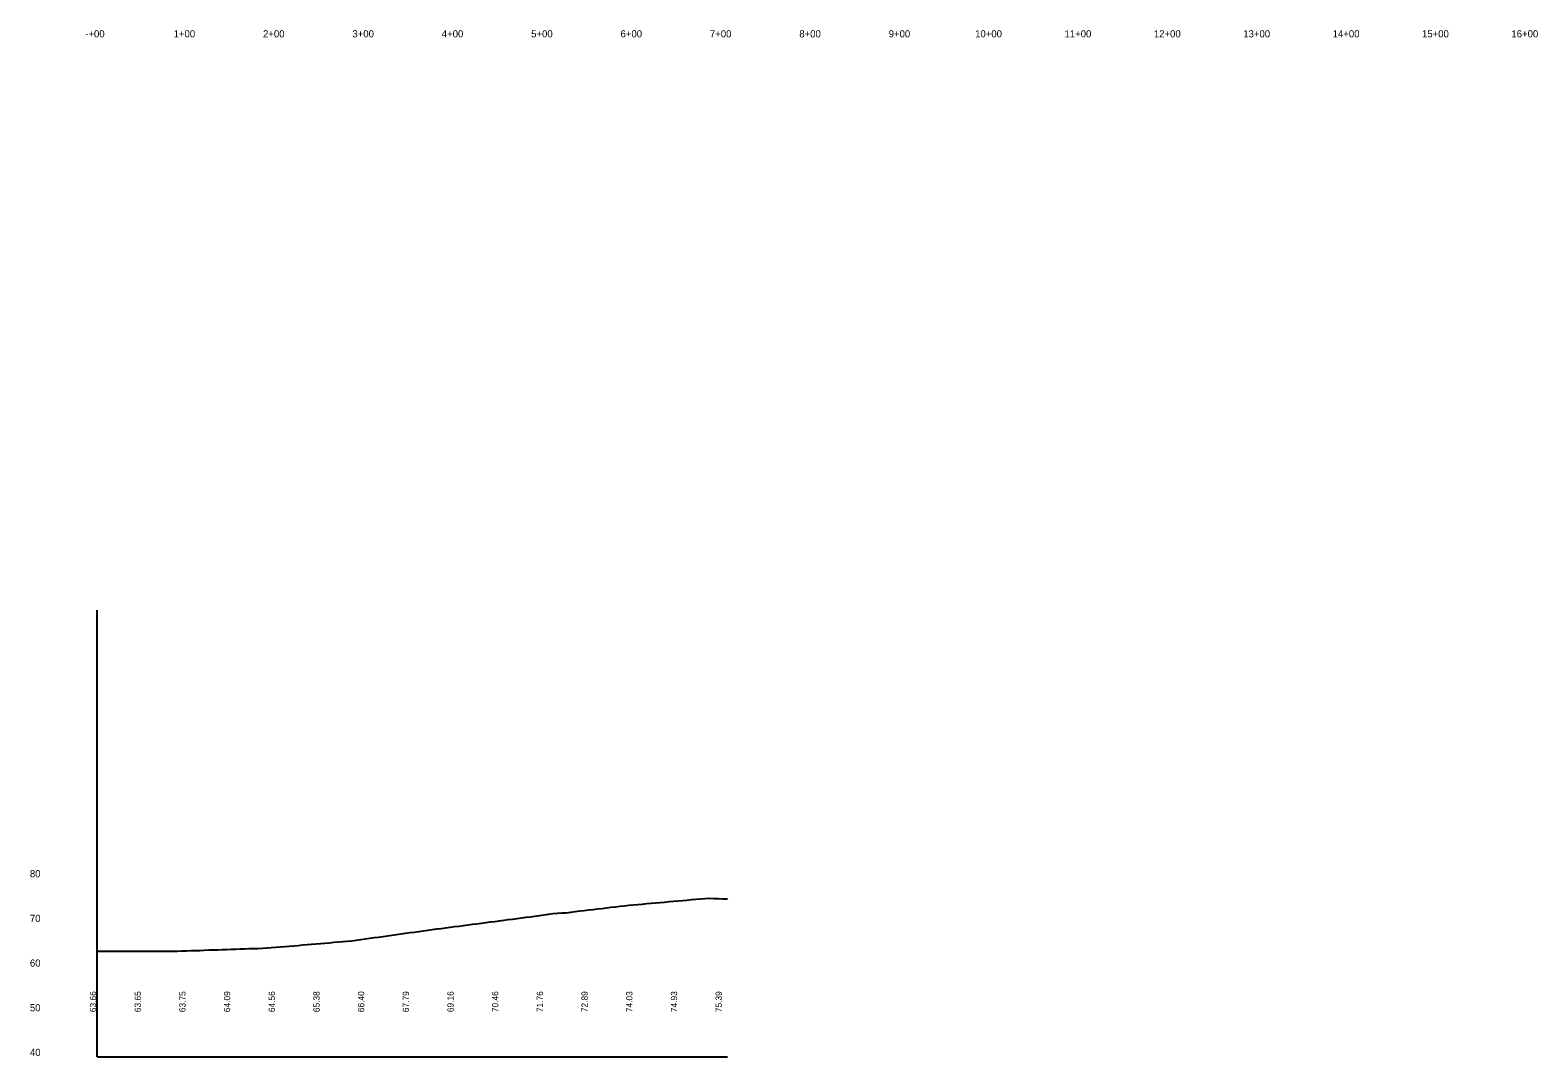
# Model space of a CAD drawing. Extents: x 2526761 to 2530854, y 882903 to 888012.
# Drawn here: x 2526764 to 2528451, y 885212 to 886361 of the extents above; entities that cross this region are included whole.
import ezdxf

# ---------------------------------------------------------------- set-up
doc = ezdxf.new("R2010")
doc.units = 0
for name, color, linetype in [('RD_DDB_ElevTX', 7, 'Continuous'), ('RD_DDB_Profile_EX', 7, 'Continuous'), ('RD_DDB_StaTX', 7, 'Continuous'), ('RD_DDB_StripGrade', 7, 'Continuous'), ('RD_GPK_Profile_Cell', 7, 'Continuous')]:
    doc.layers.add(name, color=color, linetype=linetype)

msp = doc.modelspace()

# ---------------------------------------------------------------- linework, layer by layer
at = {"layer": 'RD_DDB_Profile_EX'}
for points in [[(2527324, 885368.9), (2527329, 885369.6), (2527334, 885370.2), (2527339, 885370.9), (2527344, 885371.9), (2527349, 885372.5), (2527354, 885373), (2527359, 885373.2), (2527364, 885373.4), (2527369, 885374.2), (2527374, 885374.8), (2527379, 885375.4), (2527384, 885376), (2527389, 885376.6), (2527394, 885377.1), (2527399, 885377.7), (2527404, 885378.3), (2527409, 885378.9), (2527414, 885379.5), (2527419, 885380.1), (2527424, 885380.7), (2527429, 885381.3), (2527434, 885381.8), (2527439, 885382.2), (2527444, 885382.7), (2527449, 885383.1), (2527454, 885383.6), (2527459, 885384), (2527464, 885384.5), (2527469, 885384.9), (2527474, 885385.4), (2527479, 885385.8), (2527484, 885386.3), (2527489, 885386.7), (2527494, 885387.2), (2527499, 885387.6), (2527504, 885388.1), (2527509, 885388.5), (2527514, 885389), (2527519, 885389.5), (2527524, 885389.7), (2527529, 885389.5), (2527534, 885389.3), (2527539, 885389), (2527544, 885388.8), (2527544.4, 885388.7)], [(2526839, 885330.4), (2526864, 885330.3), (2526869, 885330.3), (2526874, 885330.3), (2526879, 885330.3), (2526884, 885330.3), (2526889, 885330.3), (2526894, 885330.3), (2526899, 885330.3), (2526904, 885330.3), (2526909, 885330.4), (2526914, 885330.4), (2526919, 885330.4), (2526924, 885330.4), (2526929, 885330.5), (2526934, 885330.6), (2526939, 885330.8), (2526944, 885331), (2526949, 885331.2), (2526954, 885331.3), (2526959, 885331.5), (2526964, 885331.7), (2526969, 885331.9), (2526974, 885332), (2526979, 885332.2), (2526984, 885332.4), (2526989, 885332.5), (2526994, 885332.7), (2526999, 885332.9), (2527004, 885333), (2527009, 885333.2), (2527014, 885333.4), (2527019, 885333.5), (2527024, 885333.7), (2527029, 885334), (2527034, 885334.5), (2527039, 885334.9), (2527044, 885335.3), (2527049, 885335.7), (2527054, 885336.1), (2527059, 885336.5), (2527064, 885336.9), (2527069, 885337.4), (2527074, 885337.8), (2527079, 885338.2), (2527084, 885338.6), (2527089, 885339), (2527094, 885339.4), (2527099, 885339.8), (2527104, 885340.3), (2527109, 885340.7), (2527114, 885341.1), (2527119, 885341.5), (2527124, 885342), (2527129, 885342.7), (2527134, 885343.4), (2527139, 885344.1), (2527144, 885344.8), (2527149, 885345.5), (2527154, 885346.2), (2527159, 885346.9), (2527164, 885347.6), (2527169, 885348.3), (2527174, 885349), (2527179, 885349.7), (2527184, 885350.4), (2527189, 885351.1), (2527194, 885351.8), (2527199, 885352.5), (2527204, 885353.2), (2527209, 885353.9), (2527214, 885354.6), (2527219, 885355.3), (2527224, 885355.9), (2527229, 885356.6), (2527234, 885357.2), (2527239, 885357.9), (2527244, 885358.5), (2527249, 885359.2), (2527254, 885359.8), (2527259, 885360.5), (2527264, 885361.1), (2527269, 885361.8), (2527274, 885362.4), (2527279, 885363.1), (2527284, 885363.7), (2527289, 885364.4), (2527294, 885365), (2527299, 885365.7), (2527304, 885366.3), (2527309, 885367), (2527314, 885367.6), (2527319, 885368.3), (2527324, 885368.9)]]:
    msp.add_lwpolyline(points, dxfattribs=at)
at = {"layer": 'RD_GPK_Profile_Cell'}
for q in [(2526839, 885712.1), (2527544.4, 885212.1), (2526839, 885212.1)]:
    msp.add_line((2526839, 885212.1), q, dxfattribs=at)

# ---------------------------------------------------------------- texts
at = {"layer": 'RD_DDB_ElevTX'}
for s, p in [('80', (2526763.9, 885413.1)), ('70', (2526763.9, 885363.1)), ('60', (2526763.9, 885313.1)), ('50', (2526763.9, 885263.1)), ('40', (2526763.9, 885213.1))]:
    msp.add_text(s, height=8, dxfattribs=at).set_placement(p)
at = {"layer": 'RD_DDB_StaTX'}
for s, p in [('-+00', (2526825.8, 886353.1)), ('1+00', (2526924.7, 886353.1)), ('2+00', (2527024.7, 886353.1)), ('3+00', (2527124.7, 886353.1)), ('4+00', (2527224.7, 886353.1)), ('5+00', (2527324.7, 886353.1)), ('6+00', (2527424.7, 886353.1)), ('7+00', (2527524.7, 886353.1)), ('8+00', (2527624.7, 886353.1)), ('9+00', (2527724.7, 886353.1)), ('10+00', (2527821.4, 886353.1)), ('11+00', (2527921.4, 886353.1)), ('12+00', (2528021.4, 886353.1)), ('13+00', (2528121.4, 886353.1)), ('14+00', (2528221.4, 886353.1)), ('15+00', (2528321.4, 886353.1)), ('16+00', (2528421.4, 886353.1))]:
    msp.add_text(s, height=8, dxfattribs=at).set_placement(p)
at = {"layer": 'RD_DDB_StripGrade'}
for s, p in [('63.66', (2526838, 885262.1)), ('63.65', (2526888, 885262.1)), ('63.75', (2526938, 885262.1)), ('64.09', (2526988, 885262.1)), ('64.56', (2527038, 885262.1)), ('65.38', (2527088, 885262.1)), ('66.40', (2527138, 885262.1)), ('67.79', (2527188, 885262.1)), ('69.16', (2527238, 885262.1)), ('70.46', (2527288, 885262.1)), ('71.76', (2527338, 885262.1)), ('72.89', (2527388, 885262.1)), ('74.03', (2527438, 885262.1)), ('74.93', (2527488, 885262.1)), ('75.39', (2527538, 885262.1))]:
    msp.add_text(s, height=7, rotation=90, dxfattribs=at).set_placement(p)
at = {"layer": 'RD_GPK_Profile_Cell'}
for s, p in [('059', (2526839, 885216.5)), ('S29', (2526839, 885215.8)), ('5900.000000', (2526839, 885215.2)), ('40', (2526839, 885214.6)), ('50', (2526839, 885214)), ('10', (2526839, 885213.3)), ('NOGAP', (2526839, 885212.7))]:
    msp.add_text(s, height=0.208, dxfattribs=at).set_placement(p)

doc.saveas('drawing.dxf')
